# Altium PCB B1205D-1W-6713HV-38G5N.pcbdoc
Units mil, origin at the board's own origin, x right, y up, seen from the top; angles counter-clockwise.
Board outline 1802.56 x 1135.88 mil, 2 copper layers (Top Layer, Bottom Layer); 16 components, 9 nets, 38 pads, 11 vias.
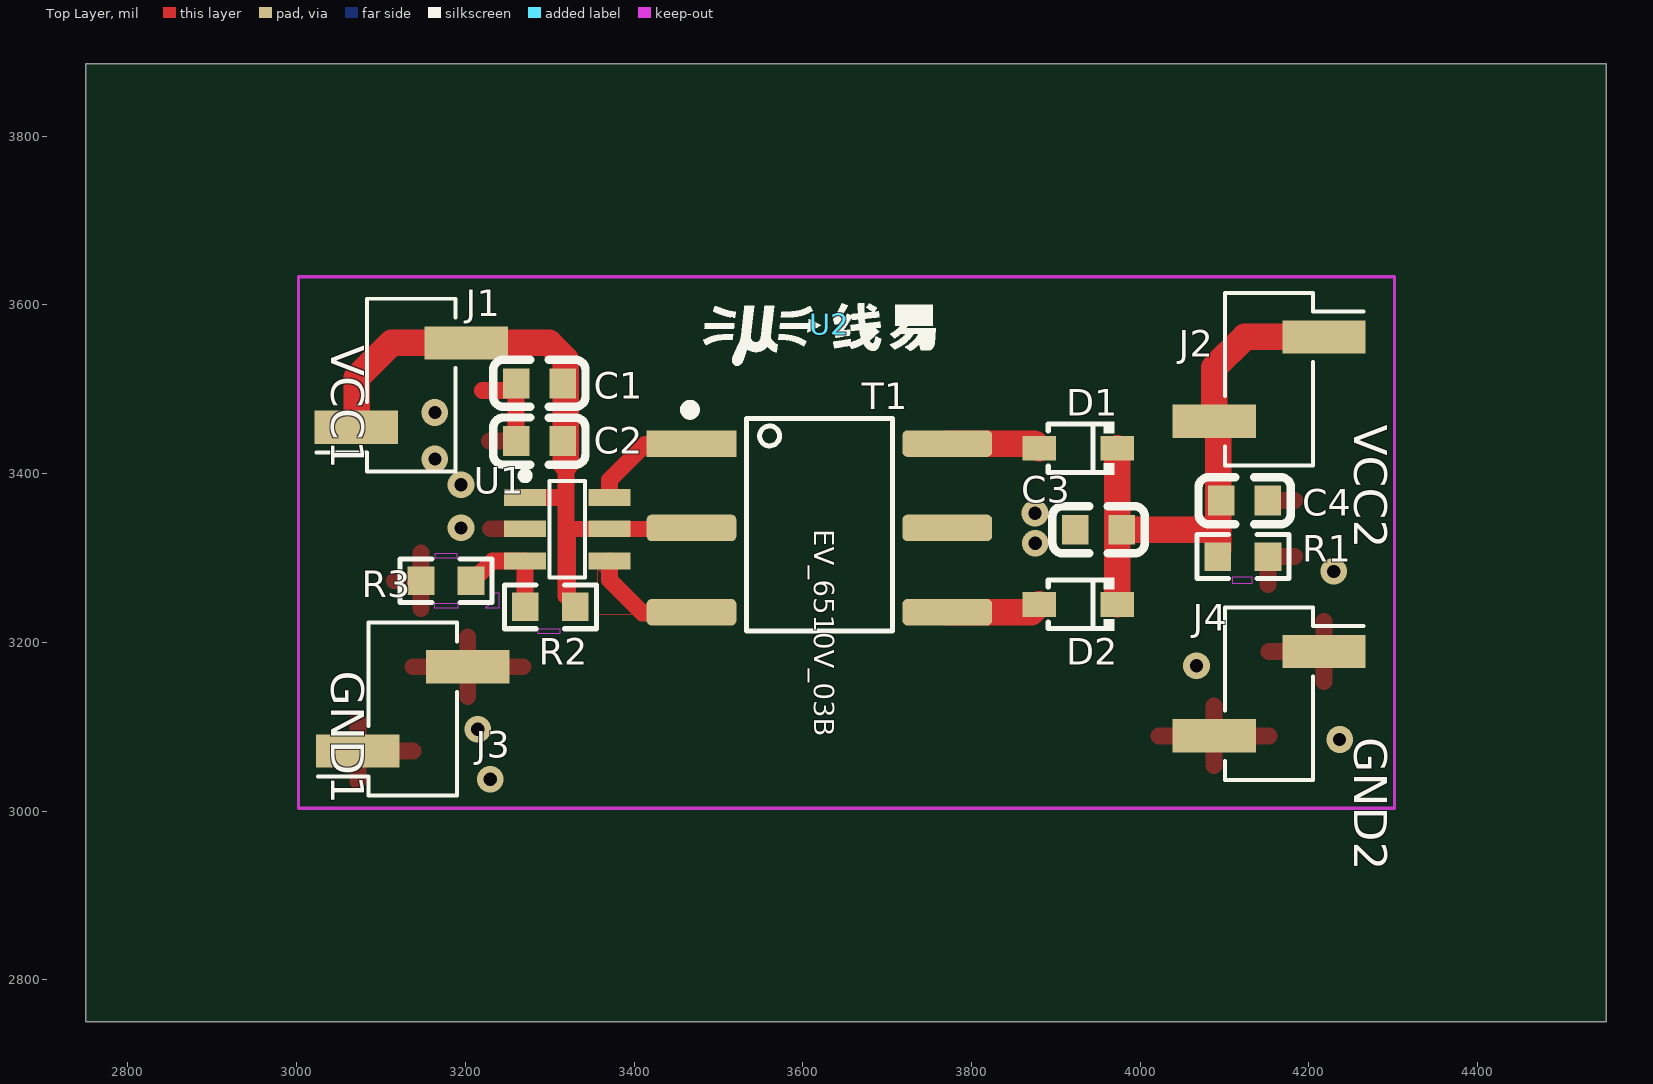
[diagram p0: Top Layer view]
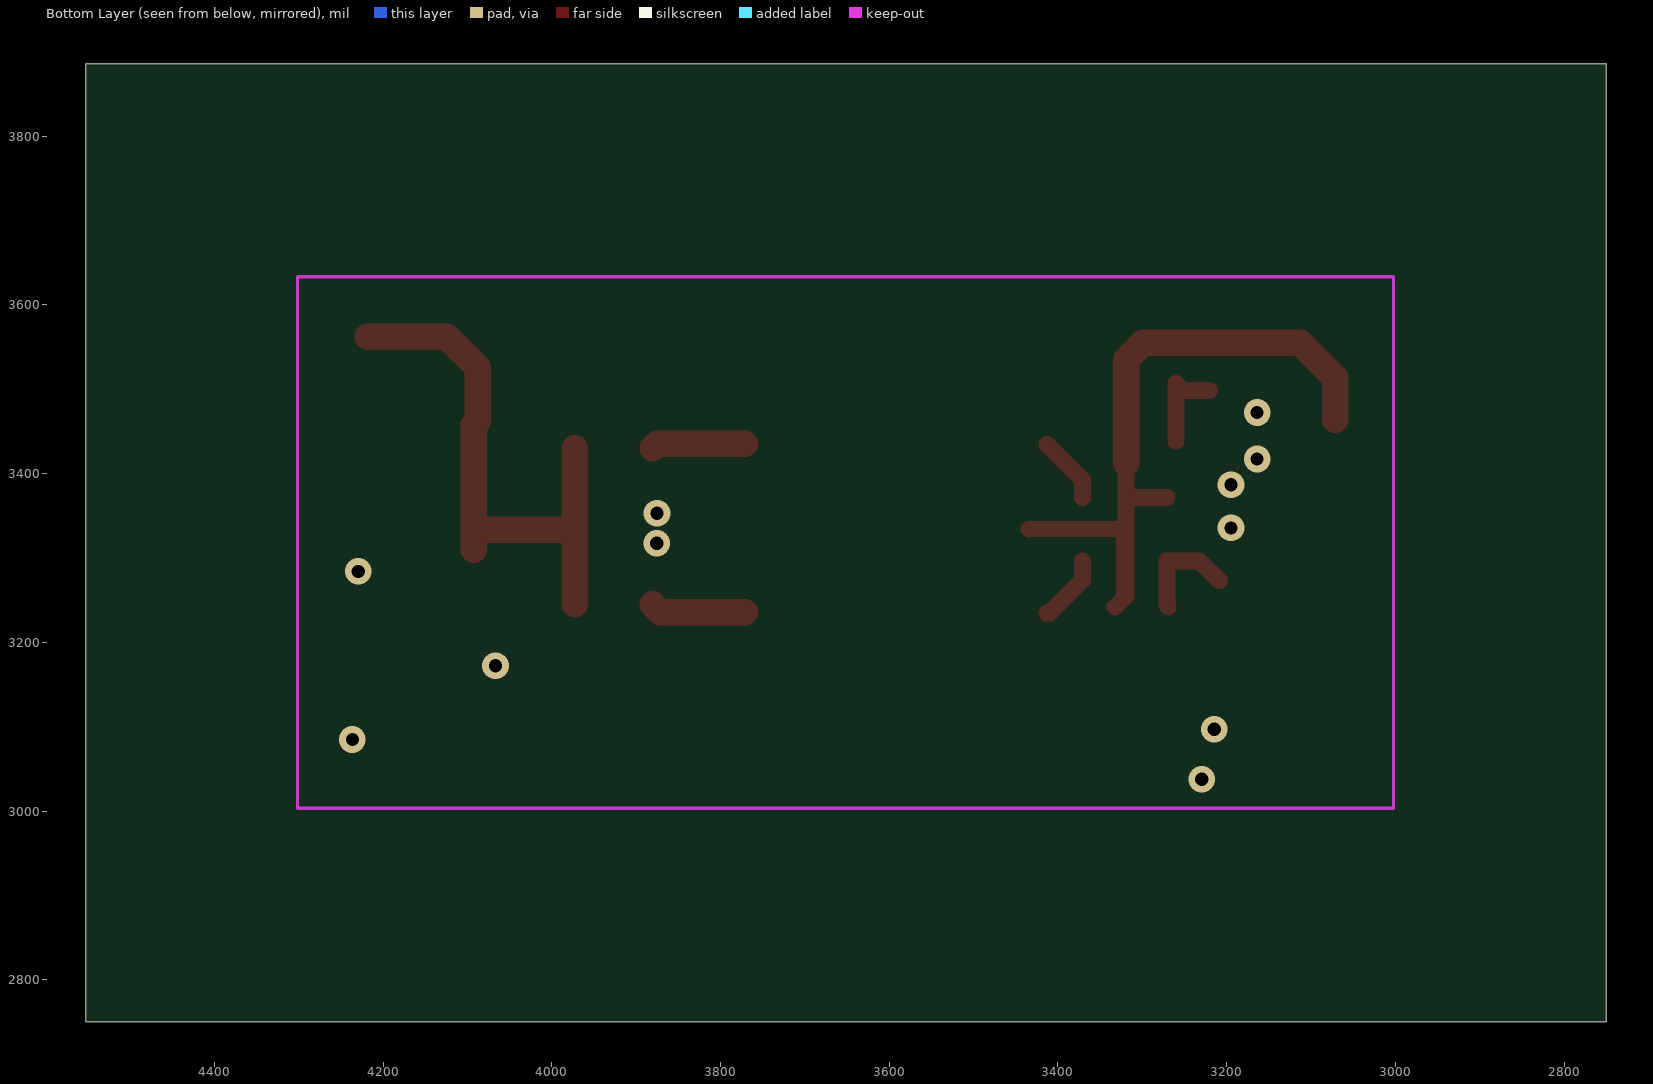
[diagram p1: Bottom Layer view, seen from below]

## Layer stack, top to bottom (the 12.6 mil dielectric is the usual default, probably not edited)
Top Layer: signal copper (thickness not stored)
Dielectric: dielectric 12.6, FR-4, Dk 4.8
Bottom Layer: signal copper (thickness not stored)

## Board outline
4552.56,2750 2750,2750 2750,3885.88 4552.56,3885.88

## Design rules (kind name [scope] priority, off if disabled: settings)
BoardOutlineClearance safeClearance [All] p0: genericclearance=10 ignorepadtopadclearanceinfootprint=FALSE except(0: Track-CutoutEdge SMDPad-CutoutEdge THPad-CutoutEdge Via-CutoutEdge Fill-CutoutEdge Region-CutoutEdge Arc-SplitContinuation Track-SplitContinuation SMDPad-SplitContinuation THPad-SplitContinuation Via-SplitContinuation Fill-SplitContinuation Poly-SplitContinuation Region-SplitContinuation Text-SplitContinuation; 11.8: Track-OutlineEdge SMDPad-OutlineEdge THPad-OutlineEdge Via-OutlineEdge Fill-OutlineEdge Region-OutlineEdge Poly-OutlineEdge Text-OutlineEdge)
Clearance safeClearance [(InNet('GND2') OR InNet('GND1') OR InNet('VCC1') OR InNet('VCC2') OR InNet('$1N17') OR InNet('$1N5') OR InNet('$1N10') OR InNet('$1N11') OR InNet('$1N9'))] p1: gap=7 ignorepadtopadclearanceinfootprint=FALSE except(0: Track-Track Track-SMDPad SMDPad-SMDPad Track-THPad SMDPad-THPad THPad-THPad Track-Via SMDPad-Via THPad-Via Via-Via Track-Fill SMDPad-Fill THPad-Fill Via-Fill Fill-Fill Track-Region SMDPad-Region THPad-Region Via-Region Fill-Region Region-Region Track-Poly SMDPad-Poly THPad-Poly Via-Poly Fill-Poly Region-Poly Poly-Poly Track-Text SMDPad-Text THPad-Text Via-Text Fill-Text Region-Text Poly-Text Text-Text Track-Hole SMDPad-Hole THPad-Hole Via-Hole Fill-Hole Region-Hole Poly-Hole Text-Hole; 11.8: Track-Sheet SMDPad-Sheet THPad-Sheet Via-Sheet Fill-Sheet Region-Sheet Poly-Sheet Text-Sheet Sheet-Hole)
DiffPairsRouting differentialPair [All] p1: maxuncoupledlength=10 minlimit=6 maxlimit=6 mostfreqgap=6 toplayer_minwidth=5 toplayer_prefwidth=10 toplayer_maxwidth=100 bottomlayer_minwidth=5 bottomlayer_prefwidth=10 bottomlayer_maxwidth=100
PasteMaskExpansion Common [All] p1: expansion=0
PlaneConnect innerPlane [All] p1: planeconnectstyle=Relief reliefexpansion=20 reliefentries=4 reliefconductorwidth=10 reliefairgap=10
PolygonConnect CopperRegion [All] p1: connectstyle=Relief reliefentries=4 reliefconductorwidth=0 polygonreliefangle="90 Angle" airgapwidth=20
PolygonConnect CopperRegion1 [All] p1: connectstyle=Relief reliefentries=4 reliefconductorwidth=20 polygonreliefangle="90 Angle" airgapwidth=15.748
PolygonConnect CopperRegion2 [All] p1: connectstyle=Direct reliefentries=4 reliefconductorwidth=0 polygonreliefangle="90 Angle" airgapwidth=20
PolygonConnect CopperRegion3 [All] p1: connectstyle=Relief reliefentries=4 reliefconductorwidth=0 polygonreliefangle="90 Angle" airgapwidth=20
PolygonConnect CopperRegion4 [All] p1: connectstyle=Relief reliefentries=4 reliefconductorwidth=0 polygonreliefangle="90 Angle" airgapwidth=20
RoutingVias viaSize [All] p1: viastyle="Through Hole" holewidth=12 minholewidth=11.8 maxholewidth=236.2 width=24 minwidth=19.7 maxwidth=393.7
SolderMaskExpansion Common [All] p1: useseparateexpansions=TRUE expansion=0 expansionbottom=0
Width trackWidth [All] p1: maxlimit=100 minlimit=5 preferedwidth=10

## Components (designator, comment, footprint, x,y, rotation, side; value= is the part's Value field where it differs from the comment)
C1 "R" C0603 3287.8,3506.99 r0 top
C2 "0603X106M250NT" C0603 3287.8,3438.49 r0 top
C3 "0603X106K100NT" C0603 3950.71,3333.37 r0 top
C4 "CC0603KRX7R9BB104" C0603 4123.89,3367.89 r180 top
D1 "B5819WS_C64886" SOD-323_L1.8-W1.3-LS2.5-RD 3926.54,3430.06 r180 top
D2 "B5819WS_C64886" SOD-323_L1.8-W1.3-LS2.5-RD 3926.54,3245.02 r180 top
J1 "Connector_Generic_Conn_01x02" Connector_PinHeader_2.54mm:PinHeader_1x02_P2.54mm_Vertical_SMD_Pin1Right 3135.83,3504.86 r180 top
J2 "Connector_Generic_Conn_01x02" Connector_PinHeader_2.54mm:PinHeader_1x02_P2.54mm_Vertical_SMD_Pin1Right 4152.76,3511.95 r0 top
J3 "Connector_Generic_Conn_01x02" Connector_PinHeader_2.54mm:PinHeader_1x02_P2.54mm_Vertical_SMD_Pin1Right 3137.8,3121.01 r180 top
J4 "Connector_Generic_Conn_01x02" Connector_PinHeader_2.54mm:PinHeader_1x02_P2.54mm_Vertical_SMD_Pin1Right 4152.76,3139.12 r0 top
R1 "RC0603FR-072K2L" R0603 4121.7,3301.56 r0 top
R2 "R" R0603 3300.79,3242.03 r0 top
R3 "RC0603FR-0710KL" R0603 3177.17,3272.97 r180 top
T1 "CMT38G5N" MYLibrary:CMT68-38 3619.76,3335.57 r0 top
U1 "CMP6713HV" MYLibrary:SOT23-6 3320.87,3334.55 r0 top
U2 "LOGO_7x1.87mm" LOGO_7x4mm 3631.95,3576.71 r0 top

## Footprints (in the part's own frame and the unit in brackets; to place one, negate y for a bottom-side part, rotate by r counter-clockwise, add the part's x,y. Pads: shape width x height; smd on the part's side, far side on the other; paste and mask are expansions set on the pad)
C0603 [mm]
  rect 0.8x0.9 smd: 1(-0.7,0) 2(0.7,0)
  silkscreen extent -1.39,-0.71 1.39,0.71
Connector_PinHeader_2.54mm:PinHeader_1x02_P2.54mm_Vertical_SMD_Pin1Right [mm]
  rect 2.51x1 smd: 1(1.655,1.27) 2(-1.655,-1.27)
  silkscreen extent -1.33,-2.6 2.85,2.6
LOGO_7x4mm [mil]
  silkscreen extent -150,-49 126,25
MYLibrary:CMT68-38 [mm]
  rect 2.7x0.8 smd: 1(-3.85,2.54)
  rrect37% 2.7x0.8 smd: 2(-3.85,0) 3(-3.85,-2.54) 4(3.85,-2.54) 5(3.85,0) 6(3.85,2.54)
  silkscreen extent -4.05,-3.1 2.2,3.71
MYLibrary:SOT23-6 [mil]
  rect 50x20 smd: 1(-50,37) 2(-50,0) 3(-50,-38) 4(50,-38) 5(50,0) 6(50,37)
  silkscreen extent -54,-58 21,67
R0603 [mil]
  rect 31.75x34.02 smd: 1(-29.66,0) 2(29.66,0)
  silkscreen extent -55,-26 55,26
SOD-323_L1.8-W1.3-LS2.5-RD [mm]
  rect 1x0.75 smd: 1(-1.173,0) 2(1.173,0)
  silkscreen extent -1.08,-0.8 0.9,0.8

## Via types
v1: diameter 31.5, hole 15.75, Top Layer to Bottom Layer, 11 vias

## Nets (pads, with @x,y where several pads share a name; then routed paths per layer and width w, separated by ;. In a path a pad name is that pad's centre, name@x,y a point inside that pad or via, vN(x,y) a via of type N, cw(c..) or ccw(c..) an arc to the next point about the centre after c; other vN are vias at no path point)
$1N5: D2.2 T1.4 | length 112.9
  Top Layer w31.5: T1.4 3870.92,3235.57 D2.2
$1N9: T1.3 U1.4 | length 81.4
  Top Layer w20: U1.4 3370.87,3273.76 3410.08,3234.55 3413.23,3234.55
$1N10: R2.1 R3.1 U1.3 | length 127.1
  Top Layer w20: R3.1@3208.66,3272.97 3232.24,3296.55 U1.3 3270.87,3243.6 R2.1@3269.29,3242.03
$1N11: T1.1 U1.6 | length 80.5
  Top Layer w20: U1.6 3370.87,3392.19 3413.23,3434.55
$1N17: D1.2 T1.6 | length 111.3
  Top Layer w31.5: T1.6 3874.86,3435.57 D1.2
GND1: C1.1 C2.1 J3.1 J3.2 R3.2 U1.2 | length 112
  Top Layer w20: 3220.34,3498.4 3251.65,3498.4 C1.1 C2.1
  other v1: 3229.53,3037.54 3214.8,3096.79 3194.88,3335.57 3194.88,3386.75 3164.02,3417.27 3164.02,3472.38
GND2: C3.1 C4.1 J4.1 J4.2 R1.2 T1.5
  other v1: 4236.33,3084.77 4066.73,3172.03 4229.53,3284 3875.71,3317.46 3875.35,3352.9
VCC1: C1.2 C2.2 J1.1 J1.2 R2.2 T1.2 U1.1 U1.5 | length 865.3
  Top Layer w20: U1.1 3316.92,3371.55 3319.29,3373.92 ; 3319.29,3412.34 3319.29,3373.92 ; R2.2@3332.28,3242.03 R2.2@3321.1,3253.21 ; T1.2@3434.57,3333.96 3321.1,3334.55 R2.2@3321.1,3253.21 ; 3319.29,3373.92 3319.29,3255.02 R2.2@3321.1,3253.21
  Top Layer w31.5: J1.1@3071.46,3463.92 3071.46,3513.72 3112.6,3554.86 J1.2 3299.21,3554.86 3319.29,3534.79 3319.29,3412.34
VCC2: C3.2 C4.2 D1.1 D2.1 J2.1 J2.2 R1.1 | length 652
  Top Layer w31.5: D2.1 D1.1 ; C3.2 4081.34,3333.37 4081.72,3333.75 ; R1.1@4092.39,3309.59 4092.39,3457.16 J2.2 4087.6,3525.53 4124.02,3561.95 J2.1

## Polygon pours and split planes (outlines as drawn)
GND1 on Top Layer (solid, remove dead copper, pour order 0): 3269.88,3509 3269.88,3233.41 3356.69,3233.41 3356.69,3004.08 3001.66,3004.08 3001.66,3372.66 3022.83,3393.84 3022.83,3509
GND1 on Bottom Layer (solid, remove dead copper, pour order 8): 3462.99,3003.29 3001.88,3003.29 3001.88,3633.21 3462.99,3633.21
GND1 on Top Layer (solid, remove dead copper, pour order 2): 3356.69,3233.41 3417.32,3233.41 3356.69,3287.19
GND2 on Bottom Layer (solid, remove dead copper, pour order 10): 4302.56,3003.92 3662.8,3005.96 3662.8,3635.88 4302.56,3633.84
GND2 on Top Layer (solid, remove dead copper, pour order 4): 3934.96,3297.94 3861.57,3297.94 3861.57,3297.78 3850.32,3309.75 3749.8,3309.75 3749.92,3356.99 3848.35,3356.99 3857.64,3372.58 3857.64,3372.74 3934.96,3372.74
GND2 on Top Layer (solid, remove dead copper, pour order 6): 4301.94,3000 3965.36,3000 3965.08,3129.67 4015.95,3129.67 4029.08,3146.99 4029.08,3280.71 4126.52,3280.71 4134.39,3292.52 4134.39,3392.13 4301.94,3392.13

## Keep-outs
Top Layer:
  region: 3286.73,3216.02 3311.93,3216.02 3311.93,3209.94 3286.73,3209.94
  region: 3163.56,3246.44 3190.77,3246.44 3190.77,3240.36 3163.56,3240.36
  region: 3164.57,3305.56 3189.76,3305.56 3189.76,3299.48 3164.57,3299.48
  region: 4109.83,3277.53 4132.37,3277.53 4132.37,3269.53 4109.83,3269.53
  region: 3223.72,3241.08 3240.5,3241.08 3240.5,3258.41 3233.86,3258.41 3231.7,3246.97
Board Outline Layer:
  lines w3.94: 3002.36,3003.29 4301.57,3003.29 4301.57,3633.21 3002.36,3633.21 3002.36,3003.29

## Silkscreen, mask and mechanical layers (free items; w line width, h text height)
Top Silkscreen Layer:
  text "VCC1" at 3041.34,3552.11 h39.37 r270
  text "VCC2" at 4253.94,3457.62 h39.37 r270
  text "EV_6510V_03B" at 3613.88,3333.75 h23.62 r270
  text "GND1" at 3041.34,3166.28 h39.37 r270
  text "GND2" at 4253.94,3087.54 h39.37 r270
